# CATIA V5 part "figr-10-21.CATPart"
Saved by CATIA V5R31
Part number: Part1
Bounding box of the stored display mesh (mm): x -60 to 60, y -90 to 70, z -46.082 to 16.155
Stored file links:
  D:\PROJECTS\Project 2021\US EDITION\CATIA V5 6R 2021\Resources\Part Files\c10_catia_v5_6r2021_prt\c10_catia_v5_6r2021_prt\figr-10-21.CATPart
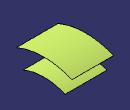
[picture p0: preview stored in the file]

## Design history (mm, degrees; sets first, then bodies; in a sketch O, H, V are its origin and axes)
Set1
  Sketch1 on yz-plane, origin (0, 0, 0), H (0, 1, 0), V (0, 0, 1)
    arc A1 centre (-10, -190) radius 206.1553 from (-90, 0) to (70, 0) cw
  Extrude1: Element1 Sketch1, Lim1 60, Lim2 60, Direction yz-plane
  Offset1: Offset Extrude1, Length 50
Body1 (main body)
